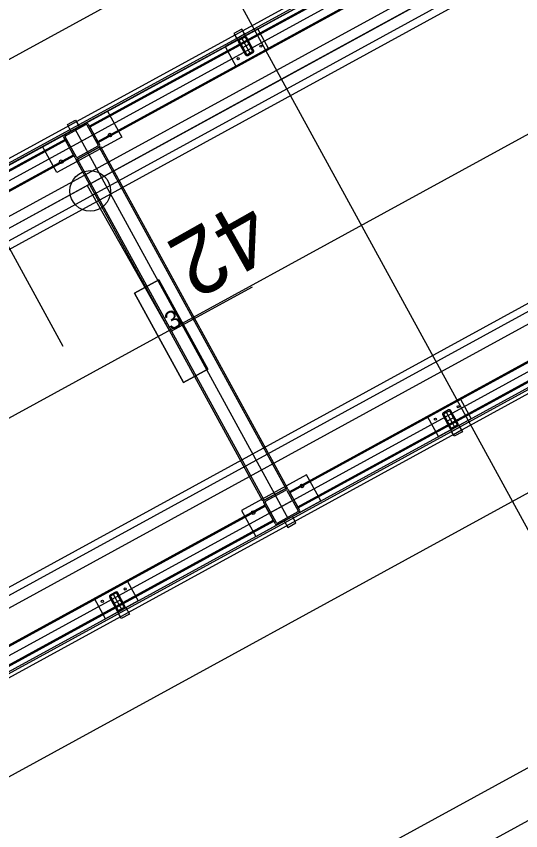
# Model space of a CAD drawing. Extents: x -783978 to -783565, y -1064821 to -1064596.
# Drawn here: x -783773.402 to -783770.678, y -1064688.948 to -1064684.549 of the extents above; entities that cross this region are included whole.
import ezdxf

# ---------------------------------------------------------------- set-up
doc = ezdxf.new("R2010")
doc.units = 0
for name, color, linetype in [('Default', 7, 'Continuous'), ('SO 01_11_01', 7, 'Continuous'), ('SO 01_20_01', 7, 'Continuous'), ('SO 01_50_01', 7, 'Continuous'), ('SO 01_74_01', 7, 'Continuous'), ('SO 01_86_04', 7, 'Continuous')]:
    doc.layers.add(name, color=color, linetype=linetype)

# ---------------------------------------------------------------- blocks, each defined once
blk = doc.blocks.new('POINT_DISPLAY')
at = {"layer": 'Default'}
blk.add_line((0, 0), (0, 0), dxfattribs=at)

msp = doc.modelspace()

# ---------------------------------------------------------------- linework, layer by layer
at = {"layer": 'SO 01_11_01'}
msp.add_line((-783768.6111, -1064691.0302), (-783772.8819, -1064683.2217), dxfattribs=at)
at = {"layer": 'SO 01_20_01'}
for p, q in [((-783735.0054, -1064663.7532), (-783787.4671, -1064692.4555)), ((-783735.2041, -1064664.4318), (-783786.7885, -1064692.6541)), ((-783786.6445, -1064692.9173), (-783735.3233, -1064664.839)), ((-783738.0171, -1064666.3812), (-783786.4402, -1064692.874)), ((-783786.421, -1064692.9091), (-783737.9979, -1064666.4163)), ((-783737.8741, -1064667.2605), (-783785.3352, -1064693.2269)), ((-783785.6531, -1064694.3127), (-783737.23, -1064667.82)), ((-783737.0912, -1064667.858), (-783785.7805, -1064694.4964)), ((-783737.2108, -1064667.855), (-783785.6339, -1064694.3478)), ((-783785.6366, -1064694.7596), (-783736.9472, -1064668.1212)), ((-783746.2961, -1064673.8055), (-783785.8354, -1064695.4379))]:
    msp.add_line(p, q, dxfattribs=at)
at = {"layer": 'SO 01_50_01'}
for p, q in [((-783786.7885, -1064692.6541), (-783725.4827, -1064659.1131)), ((-783773.6292, -1064685.4546), (-783769.2428, -1064683.0547)), ((-783773.6292, -1064685.4547), (-783769.2427, -1064683.0548)), ((-783773.6292, -1064685.4547), (-783769.2427, -1064683.0548)), ((-783773.1492, -1064686.3319), (-783774.1092, -1064684.5773))]:
    msp.add_line(p, q, dxfattribs=at)
for points in [[(-783784.7751, -1064696.3401), (-783745.2333, -1064674.7064)], [(-783784.6553, -1064696.5595), (-783745.1133, -1064674.9257)]]:
    msp.add_lwpolyline(points, dxfattribs=at)
at = {"layer": 'SO 01_74_01'}
for p, q in [((-783735.2185, -1064664.4055), (-783786.6099, -1064692.5222)), ((-783786.6003, -1064692.5398), (-783735.2089, -1064664.423)), ((-783785.4388, -1064694.6628), (-783745.8293, -1064672.9921)), ((-783745.8197, -1064673.0096), (-783785.4292, -1064694.6803)), ((-783770.4415, -1064683.739), (-783773.0075, -1064685.1429)), ((-783770.4384, -1064683.7445), (-783773.0045, -1064685.1485)), ((-783772.9625, -1064685.2251), (-783770.3965, -1064683.8212)), ((-783772.9595, -1064685.2307), (-783770.3935, -1064683.8267)), ((-783772.1834, -1064684.6179), (-783772.2272, -1064684.6419)), ((-783772.2272, -1064684.6419), (-783772.208, -1064684.677)), ((-783772.1786, -1064684.6267), (-783772.2224, -1064684.6507)), ((-783772.1642, -1064684.653), (-783772.1834, -1064684.6179)), ((-783772.169, -1064684.6443), (-783772.1786, -1064684.6267)), ((-783772.2224, -1064684.6507), (-783772.2128, -1064684.6682)), ((-783772.2128, -1064684.6682), (-783772.169, -1064684.6443)), ((-783772.208, -1064684.677), (-783772.1642, -1064684.653)), ((-783773.1264, -1064685.1339), (-783773.0826, -1064685.1099)), ((-783773.0826, -1064685.1099), (-783773.0634, -1064685.145)), ((-783773.1072, -1064685.169), (-783773.1264, -1064685.1339)), ((-783773.0634, -1064685.145), (-783773.1072, -1064685.169)), ((-783773.0075, -1064685.1429), (-783772.9595, -1064685.2307)), ((-783773.0045, -1064685.1485), (-783772.9625, -1064685.2251)), ((-783773.1391, -1064685.2149), (-783775.7052, -1064686.6188)), ((-783773.1361, -1064685.2205), (-783775.7021, -1064686.6244)), ((-783773.0911, -1064685.3027), (-783773.1391, -1064685.2149)), ((-783773.0941, -1064685.2971), (-783773.1361, -1064685.2205)), ((-783773.0791, -1064685.3246), (-783772.9475, -1064685.2526)), ((-783773.0721, -1064685.3207), (-783772.9545, -1064685.2564)), ((-783772.9545, -1064685.2564), (-783771.9466, -1064687.0987)), ((-783772.9475, -1064685.2526), (-783771.9396, -1064687.0949)), ((-783775.6602, -1064686.701), (-783773.0941, -1064685.2971)), ((-783775.6572, -1064686.7066), (-783773.0911, -1064685.3027)), ((-783772.0712, -1064687.1669), (-783773.0791, -1064685.3246)), ((-783772.0641, -1064687.163), (-783773.0721, -1064685.3207)), ((-783769.3615, -1064685.7129), (-783771.9276, -1064687.1168)), ((-783769.3585, -1064685.7184), (-783771.9245, -1064687.1223)), ((-783771.8826, -1064687.199), (-783769.3165, -1064685.7951)), ((-783771.8796, -1064687.2045), (-783769.3135, -1064685.8006)), ((-783771.0561, -1064686.7825), (-783771.0122, -1064686.7585)), ((-783771.0369, -1064686.8176), (-783771.0561, -1064686.7825)), ((-783771.0513, -1064686.7913), (-783771.0074, -1064686.7673)), ((-783771.0417, -1064686.8088), (-783771.0513, -1064686.7913)), ((-783770.9978, -1064686.7848), (-783771.0417, -1064686.8088)), ((-783770.993, -1064686.7936), (-783771.0369, -1064686.8176)), ((-783771.0122, -1064686.7585), (-783770.993, -1064686.7936)), ((-783771.0074, -1064686.7673), (-783770.9978, -1064686.7848)), ((-783771.9396, -1064687.0949), (-783772.0712, -1064687.1669)), ((-783771.9466, -1064687.0987), (-783772.0641, -1064687.163)), ((-783771.9276, -1064687.1168), (-783771.8796, -1064687.2045)), ((-783771.9245, -1064687.1223), (-783771.8826, -1064687.199)), ((-783772.0592, -1064687.1888), (-783774.6252, -1064688.5927)), ((-783772.0112, -1064687.2765), (-783772.0592, -1064687.1888)), ((-783772.0561, -1064687.1943), (-783774.6222, -1064688.5983)), ((-783772.0142, -1064687.271), (-783772.0561, -1064687.1943)), ((-783774.5802, -1064688.6749), (-783772.0142, -1064687.271)), ((-783774.5772, -1064688.6805), (-783772.0112, -1064687.2765)), ((-783771.9114, -1064687.2505), (-783771.9553, -1064687.2745)), ((-783771.9553, -1064687.2745), (-783771.9361, -1064687.3096)), ((-783771.8922, -1064687.2856), (-783771.9114, -1064687.2505)), ((-783771.9361, -1064687.3096), (-783771.8922, -1064687.2856)), ((-783772.8545, -1064687.7664), (-783772.8107, -1064687.7424)), ((-783772.8497, -1064687.7752), (-783772.8059, -1064687.7512)), ((-783772.8107, -1064687.7424), (-783772.7915, -1064687.7775)), ((-783772.8059, -1064687.7512), (-783772.7963, -1064687.7688)), ((-783772.8353, -1064687.8015), (-783772.8545, -1064687.7664)), ((-783772.8401, -1064687.7928), (-783772.8497, -1064687.7752)), ((-783772.7963, -1064687.7688), (-783772.8401, -1064687.7928)), ((-783772.7915, -1064687.7775), (-783772.8353, -1064687.8015))]:
    msp.add_line(p, q, dxfattribs=at)
for points in [[(-783735.1681, -1064664.4976), (-783787.4762, -1064693.1159)], [(-783734.0882, -1064666.4715), (-783786.3963, -1064695.0898)], [(-783772.2035, -1064684.6853), (-783772.1646, -1064684.7565)], [(-783772.1724, -1064684.6576), (-783772.1997, -1064684.6725)], [(-783772.198, -1064684.6823), (-783772.159, -1064684.7534)], [(-783772.1694, -1064684.6631), (-783772.1967, -1064684.678)], [(-783772.1861, -1064684.665), (-783772.1381, -1064684.7528)], [(-783772.1262, -1064684.7355), (-783772.1651, -1064684.6643)], [(-783772.1207, -1064684.7325), (-783772.1596, -1064684.6613)], [(-783772.1402, -1064684.6969), (-783772.184, -1064684.7209)], [(-783772.1548, -1064684.7547), (-783772.1275, -1064684.7398)], [(-783772.1517, -1064684.7602), (-783772.1244, -1064684.7453)], [(-783773.1406, -1064685.1872), (-783773.03, -1064685.1268)], [(-783773.1367, -1064685.1942), (-783773.0262, -1064685.1338)], [(-783773.0853, -1064685.157), (-783771.9334, -1064687.2625)], [(-783773.0853, -1064685.157), (-783773.0133, -1064685.2886)], [(-783773.0208, -1064685.1354), (-783772.9603, -1064685.2459)], [(-783773.0137, -1064685.1315), (-783772.9533, -1064685.2421)], [(-783773.0849, -1064685.3141), (-783773.1453, -1064685.2035)], [(-783773.0778, -1064685.3102), (-783773.1383, -1064685.1997)], [(-783772.9835, -1064685.1868), (-783773.1151, -1064685.2588)], [(-783772.9619, -1064685.2513), (-783773.0724, -1064685.3118)], [(-783772.958, -1064685.2583), (-783773.0686, -1064685.3188)], [(-783771.0996, -1064686.7031), (-783771.0606, -1064686.7742)], [(-783771.0685, -1064686.6753), (-783771.0958, -1064686.6902)], [(-783771.094, -1064686.7), (-783771.0551, -1064686.7712)], [(-783771.0655, -1064686.6808), (-783771.0928, -1064686.6958)], [(-783771.0822, -1064686.6828), (-783771.0342, -1064686.7705)], [(-783771.0223, -1064686.7532), (-783771.0612, -1064686.6821)], [(-783771.0168, -1064686.7502), (-783771.0557, -1064686.6791)], [(-783771.0362, -1064686.7146), (-783771.0801, -1064686.7386)], [(-783771.0508, -1064686.7724), (-783771.0235, -1064686.7575)], [(-783771.0478, -1064686.778), (-783771.0205, -1064686.763)], [(-783772.0606, -1064687.1611), (-783771.9501, -1064687.1006)], [(-783771.9338, -1064687.1054), (-783771.8733, -1064687.216)], [(-783772.0568, -1064687.1681), (-783771.9463, -1064687.1077)], [(-783772.0054, -1064687.1309), (-783771.9334, -1064687.2625)], [(-783771.9408, -1064687.1093), (-783771.8804, -1064687.2198)], [(-783772.0049, -1064687.2879), (-783772.0654, -1064687.1774)], [(-783771.9979, -1064687.2841), (-783772.0584, -1064687.1736)], [(-783771.9036, -1064687.1607), (-783772.0352, -1064687.2327)], [(-783771.8819, -1064687.2252), (-783771.9925, -1064687.2857)], [(-783771.8781, -1064687.2322), (-783771.9886, -1064687.2927)], [(-783772.8669, -1064687.6593), (-783772.8942, -1064687.6742)], [(-783772.8639, -1064687.6648), (-783772.8912, -1064687.6797)], [(-783772.8806, -1064687.6667), (-783772.8326, -1064687.7544)], [(-783772.8207, -1064687.7372), (-783772.8596, -1064687.666)], [(-783772.8152, -1064687.7342), (-783772.8541, -1064687.663)], [(-783772.898, -1064687.687), (-783772.8591, -1064687.7582)], [(-783772.8925, -1064687.684), (-783772.8535, -1064687.7551)], [(-783772.8347, -1064687.6986), (-783772.8785, -1064687.7226)], [(-783772.8493, -1064687.7564), (-783772.822, -1064687.7415)], [(-783772.8462, -1064687.7619), (-783772.8189, -1064687.747)]]:
    msp.add_lwpolyline(points, dxfattribs=at)
for points in [[(-783772.0984, -1064684.617), (-783772.2738, -1064684.713), (-783772.2162, -1064684.8183), (-783772.0408, -1064684.7223)], [(-783772.8331, -1064685.2014), (-783773.184, -1064685.3934), (-783773.2608, -1064685.253), (-783772.9098, -1064685.061)], [(-783770.9464, -1064686.7225), (-783771.1219, -1064686.8185), (-783771.1795, -1064686.7132), (-783771.004, -1064686.6172)], [(-783771.8347, -1064687.0261), (-783772.1856, -1064687.2181), (-783772.1088, -1064687.3585), (-783771.7579, -1064687.1665)], [(-783772.7449, -1064687.7064), (-783772.9203, -1064687.8024), (-783772.9779, -1064687.6972), (-783772.8025, -1064687.6012)]]:
    msp.add_lwpolyline(points, close=True, dxfattribs=at)
for centre, radius in [((-783772.0815, -1064684.7104), 0.006), ((-783772.2043, -1064684.7776), 0.006), ((-783772.8961, -1064685.1903), 0.01), ((-783773.1593, -1064685.3343), 0.01), ((-783771.0159, -1064686.658), 0.006), ((-783771.1388, -1064686.7251), 0.006), ((-783771.8594, -1064687.0852), 0.01), ((-783772.1226, -1064687.2292), 0.01), ((-783772.8144, -1064687.6419), 0.006), ((-783772.9372, -1064687.7091), 0.006)]:
    msp.add_circle(centre, radius, dxfattribs=at)
for centre, radius, start, end in [((-783772.1952, -1064684.6808), 0.00945, 118.6835, 208.6835), ((-783772.1952, -1064684.6808), 0.00315, 118.6835, 208.6835), ((-783772.1679, -1064684.6658), 0.00945, 28.6835, 118.6835), ((-783772.1679, -1064684.6658), 0.00315, 28.6835, 118.6835), ((-783772.1563, -1064684.7519), 0.00945, 208.6835, 298.6835), ((-783772.1563, -1064684.7519), 0.00315, 208.6835, 298.6835), ((-783772.129, -1064684.737), 0.00315, 298.6835, 28.6835), ((-783772.129, -1064684.737), 0.00945, 298.6835, 28.6835), ((-783773.0243, -1064685.1373), 0.012, 28.6835, 118.6835), ((-783773.0243, -1064685.1373), 0.004, 28.6835, 118.6835), ((-783773.1348, -1064685.1978), 0.012, 118.6835, 208.6835), ((-783773.1348, -1064685.1978), 0.004, 118.6835, 208.6835), ((-783772.9638, -1064685.2478), 0.004, 298.6835, 28.6835), ((-783772.9638, -1064685.2478), 0.012, 298.6835, 28.6835), ((-783773.0743, -1064685.3083), 0.012, 208.6835, 298.6835), ((-783773.0743, -1064685.3083), 0.004, 208.6835, 298.6835), ((-783771.0913, -1064686.6985), 0.00945, 118.6835, 208.6835), ((-783771.0913, -1064686.6985), 0.00315, 118.6835, 208.6835), ((-783771.064, -1064686.6836), 0.00945, 28.6835, 118.6835), ((-783771.064, -1064686.6836), 0.00315, 28.6835, 118.6835), ((-783771.0251, -1064686.7548), 0.00315, 298.6835, 28.6835), ((-783771.0251, -1064686.7548), 0.00945, 298.6835, 28.6835), ((-783771.0523, -1064686.7697), 0.00945, 208.6835, 298.6835), ((-783771.0523, -1064686.7697), 0.00315, 208.6835, 298.6835), ((-783771.9443, -1064687.1112), 0.012, 28.6835, 118.6835), ((-783771.9443, -1064687.1112), 0.004, 28.6835, 118.6835), ((-783772.0549, -1064687.1716), 0.012, 118.6835, 208.6835), ((-783772.0549, -1064687.1716), 0.004, 118.6835, 208.6835), ((-783771.8839, -1064687.2217), 0.004, 298.6835, 28.6835), ((-783771.8839, -1064687.2217), 0.012, 298.6835, 28.6835), ((-783771.9944, -1064687.2822), 0.012, 208.6835, 298.6835), ((-783771.9944, -1064687.2822), 0.004, 208.6835, 298.6835), ((-783772.8897, -1064687.6825), 0.00945, 118.6835, 208.6835), ((-783772.8624, -1064687.6675), 0.00945, 28.6835, 118.6835), ((-783772.8624, -1064687.6675), 0.00315, 28.6835, 118.6835), ((-783772.8897, -1064687.6825), 0.00315, 118.6835, 208.6835), ((-783772.8508, -1064687.7536), 0.00945, 208.6835, 298.6835), ((-783772.8508, -1064687.7536), 0.00315, 208.6835, 298.6835), ((-783772.8235, -1064687.7387), 0.00315, 298.6835, 28.6835), ((-783772.8235, -1064687.7387), 0.00945, 298.6835, 28.6835)]:
    msp.add_arc(centre, radius, start, end, dxfattribs=at)
at = {"layer": 'SO 01_86_04'}
for p, q in [((-783773.0187, -1064685.4625), (-783772.5585, -1064686.2772)), ((-783772.6323, -1064685.9722), (-783772.7639, -1064686.0442)), ((-783772.6323, -1064685.9722), (-783772.7639, -1064686.0442)), ((-783772.7639, -1064686.0442), (-783772.6323, -1064685.9722)), ((-783772.7639, -1064686.0442), (-783772.6323, -1064685.9722)), ((-783772.3684, -1064686.4547), (-783772.6323, -1064685.9722)), ((-783772.3684, -1064686.4547), (-783772.6323, -1064685.9722)), ((-783772.6323, -1064685.9722), (-783772.3684, -1064686.4547)), ((-783772.6323, -1064685.9722), (-783772.3684, -1064686.4547)), ((-783772.7639, -1064686.0442), (-783772.4999, -1064686.5267)), ((-783772.7639, -1064686.0442), (-783772.4999, -1064686.5267)), ((-783772.4999, -1064686.5267), (-783772.7639, -1064686.0442)), ((-783772.4999, -1064686.5267), (-783772.7639, -1064686.0442)), ((-783772.5661, -1064686.2494), (-783772.1275, -1064686.0095)), ((-783772.4999, -1064686.5267), (-783772.3684, -1064686.4547)), ((-783772.4999, -1064686.5267), (-783772.3684, -1064686.4547)), ((-783772.3684, -1064686.4547), (-783772.4999, -1064686.5267)), ((-783772.3684, -1064686.4547), (-783772.4999, -1064686.5267))]:
    msp.add_line(p, q, dxfattribs=at)
for points in [[(-783738.3222, -1064666.4797), (-783740.5325, -1064667.689), (-783743.1715, -1064669.1328), (-783745.7538, -1064670.5456), (-783748.4385, -1064672.0145), (-783751.0413, -1064673.4385), (-783753.6847, -1064674.8847), (-783756.3281, -1064676.3309), (-783758.9715, -1064677.7772), (-783761.6149, -1064679.2234), (-783764.2583, -1064680.6696), (-783766.9018, -1064682.1159), (-783769.4633, -1064683.5173), (-783772.109, -1064684.9648), (-783774.7882, -1064686.4306), (-783778.1382, -1064688.2722), (-783783.8139, -1064691.3971), (-783785.747, -1064692.4898)], [(-783747.063, -1064670.9765), (-783746.9575, -1064671.1681), (-783786.6893, -1064692.8619), (-783786.185, -1064693.7636)]]:
    msp.add_lwpolyline(points, dxfattribs=at)
msp.add_circle((-783773.0031, -1064685.4923), 0.1097, dxfattribs=at)

# ---------------------------------------------------------------- block references
at = {"layer": 'SO 01_86_04', "xscale": 0.010000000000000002, "yscale": 0.009999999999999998, "rotation": 28.683491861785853}
for p in [(-783772.6323, -1064685.9722), (-783772.6323, -1064685.9722), (-783772.7639, -1064686.0442), (-783772.7639, -1064686.0442), (-783772.3684, -1064686.4547), (-783772.3684, -1064686.4547), (-783772.4999, -1064686.5267), (-783772.4999, -1064686.5267)]:
    msp.add_blockref('POINT_DISPLAY', p, dxfattribs=at)

# ---------------------------------------------------------------- texts
at = {"layer": 'SO 01_86_04'}
for s, height, rotation, p in [('42', 0.351, 209.46, (-783772.1527, -1064685.5235)), ('3', 0.1, 28.6835, (-783772.5661, -1064686.2494))]:
    msp.add_text(s, height=height, rotation=rotation, dxfattribs=at).set_placement(p)

doc.saveas('drawing.dxf')
